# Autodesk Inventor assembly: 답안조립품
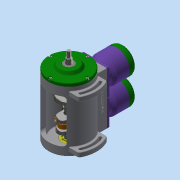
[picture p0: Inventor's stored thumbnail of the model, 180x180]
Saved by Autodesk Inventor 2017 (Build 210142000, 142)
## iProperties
Part Number: 답안조립품
Material: 일반
Document SubType Name: Assembly
Designer: Administrator
Author: Administrator
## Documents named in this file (16)
- C:\Users\Administrator\Desktop\620106V1024\답안조립품.iam
- C:\Users\Administrator\Desktop\620106V1024\너트 M4.ipt
- C:\Users\Administrator\Desktop\620106V1024\베어링 6303.ipt
- C:\Users\Administrator\Desktop\620106V1024\본체.ipt
- C:\Users\Administrator\Desktop\620106V1024\볼트 M4 x 12.ipt
- C:\Users\Administrator\Desktop\620106V1024\볼트 M5 x 20.ipt
- C:\Users\Administrator\Desktop\620106V1024\실린더.ipt
- C:\Users\Administrator\Desktop\620106V1024\실린더헤드.ipt
- C:\Users\Administrator\Desktop\620106V1024\앞커버.ipt
- C:\Users\Administrator\Desktop\620106V1024\오일 실 17 x 32 x 8.ipt
- C:\Users\Administrator\Desktop\620106V1024\육각 머리 볼트 M4 x 16.ipt
- C:\Users\Administrator\Desktop\620106V1024\커넥팅로드 엔드.ipt
- C:\Users\Administrator\Desktop\620106V1024\커넥팅로드.ipt
- C:\Users\Administrator\Desktop\620106V1024\크랭크축.ipt
- C:\Users\Administrator\Desktop\620106V1024\피스톤.ipt
- C:\Users\Administrator\Desktop\620106V1024\피스톤핀.ipt
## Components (4 placed, 2 different names)
1. 피스톤:1
2. 피스톤핀:1
3. 피스톤:2
4. 피스톤핀:2
